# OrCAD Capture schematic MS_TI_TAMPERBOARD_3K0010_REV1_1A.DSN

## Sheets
1 Pg02: Tamper Test Board: size C; title: AM437x Tamper Test Board; rev: 1.1A; company: Texas Instruments; note: am437x_tamperboard_3k0010_rev1_1a.dsn; note: ARM MPU BU; note: Final
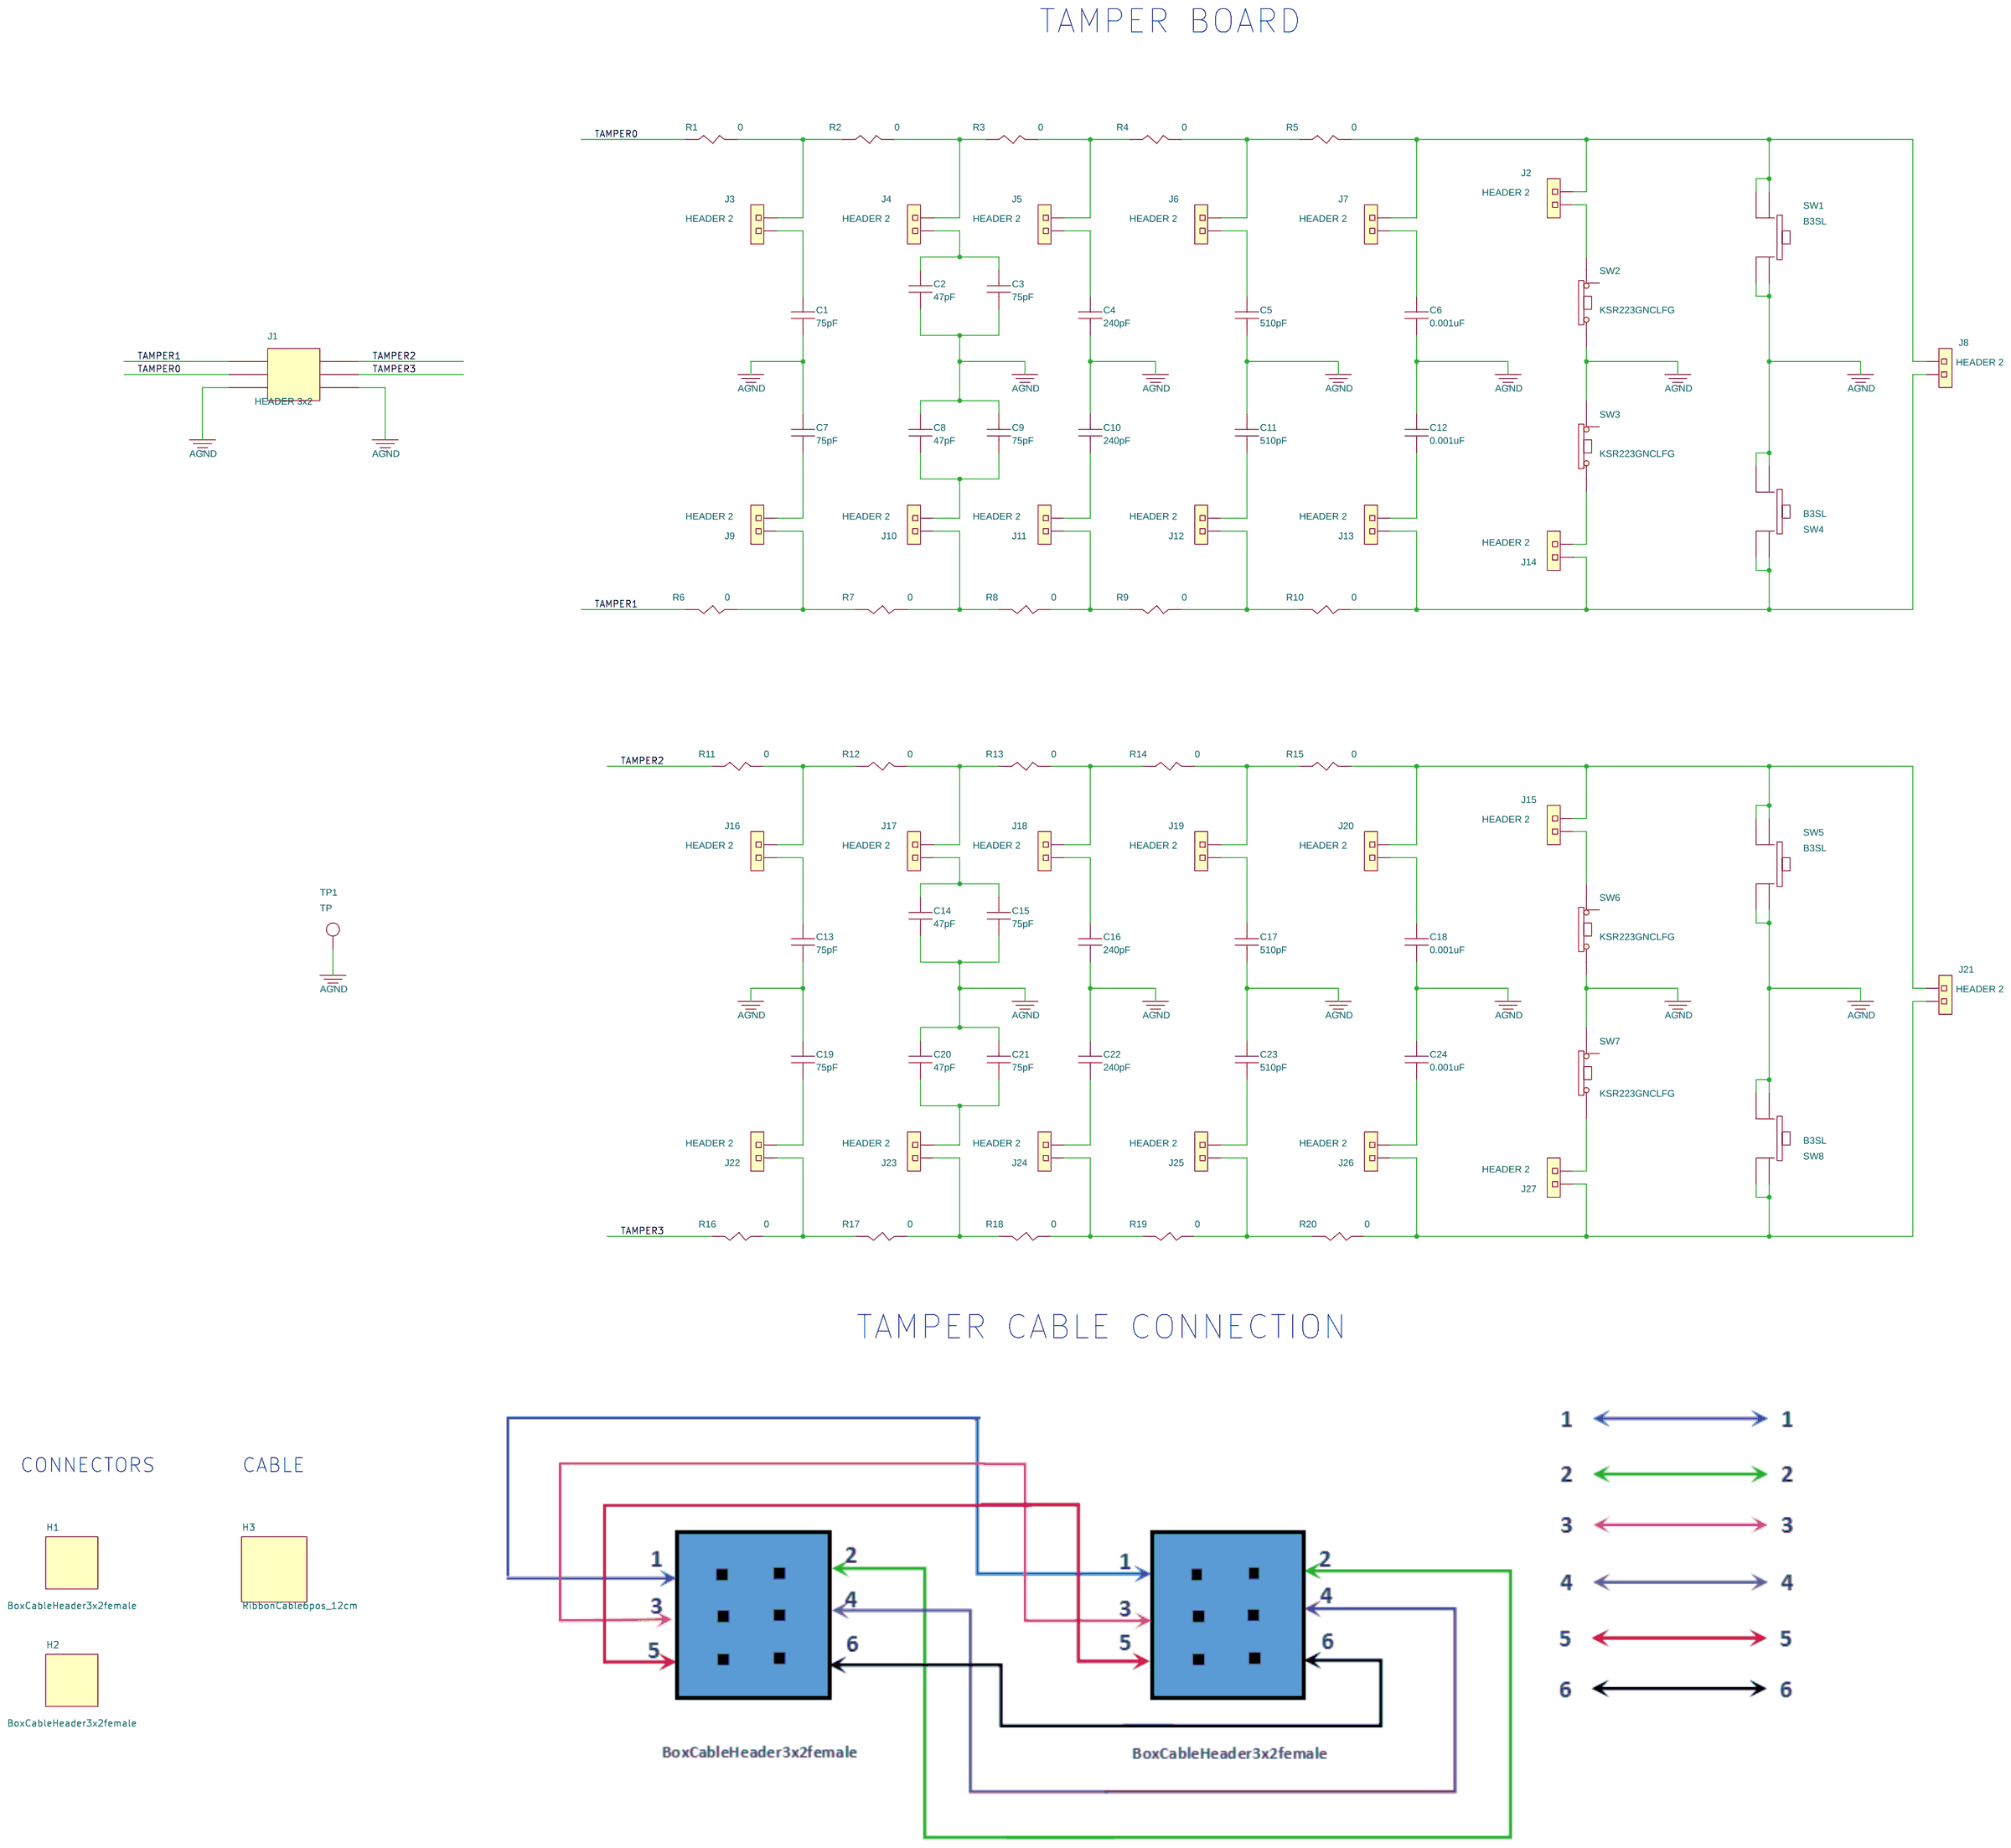
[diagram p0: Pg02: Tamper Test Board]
2 Pg01: Title
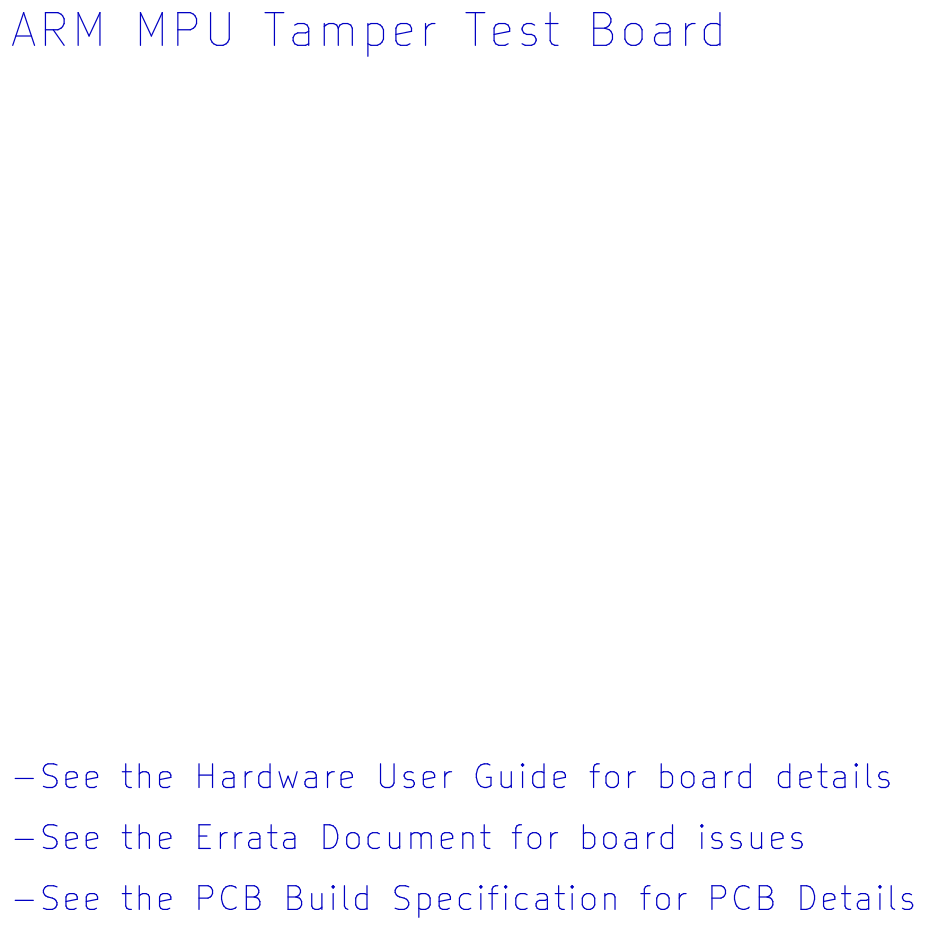
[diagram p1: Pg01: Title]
3 Pg03: Hardware Schematics
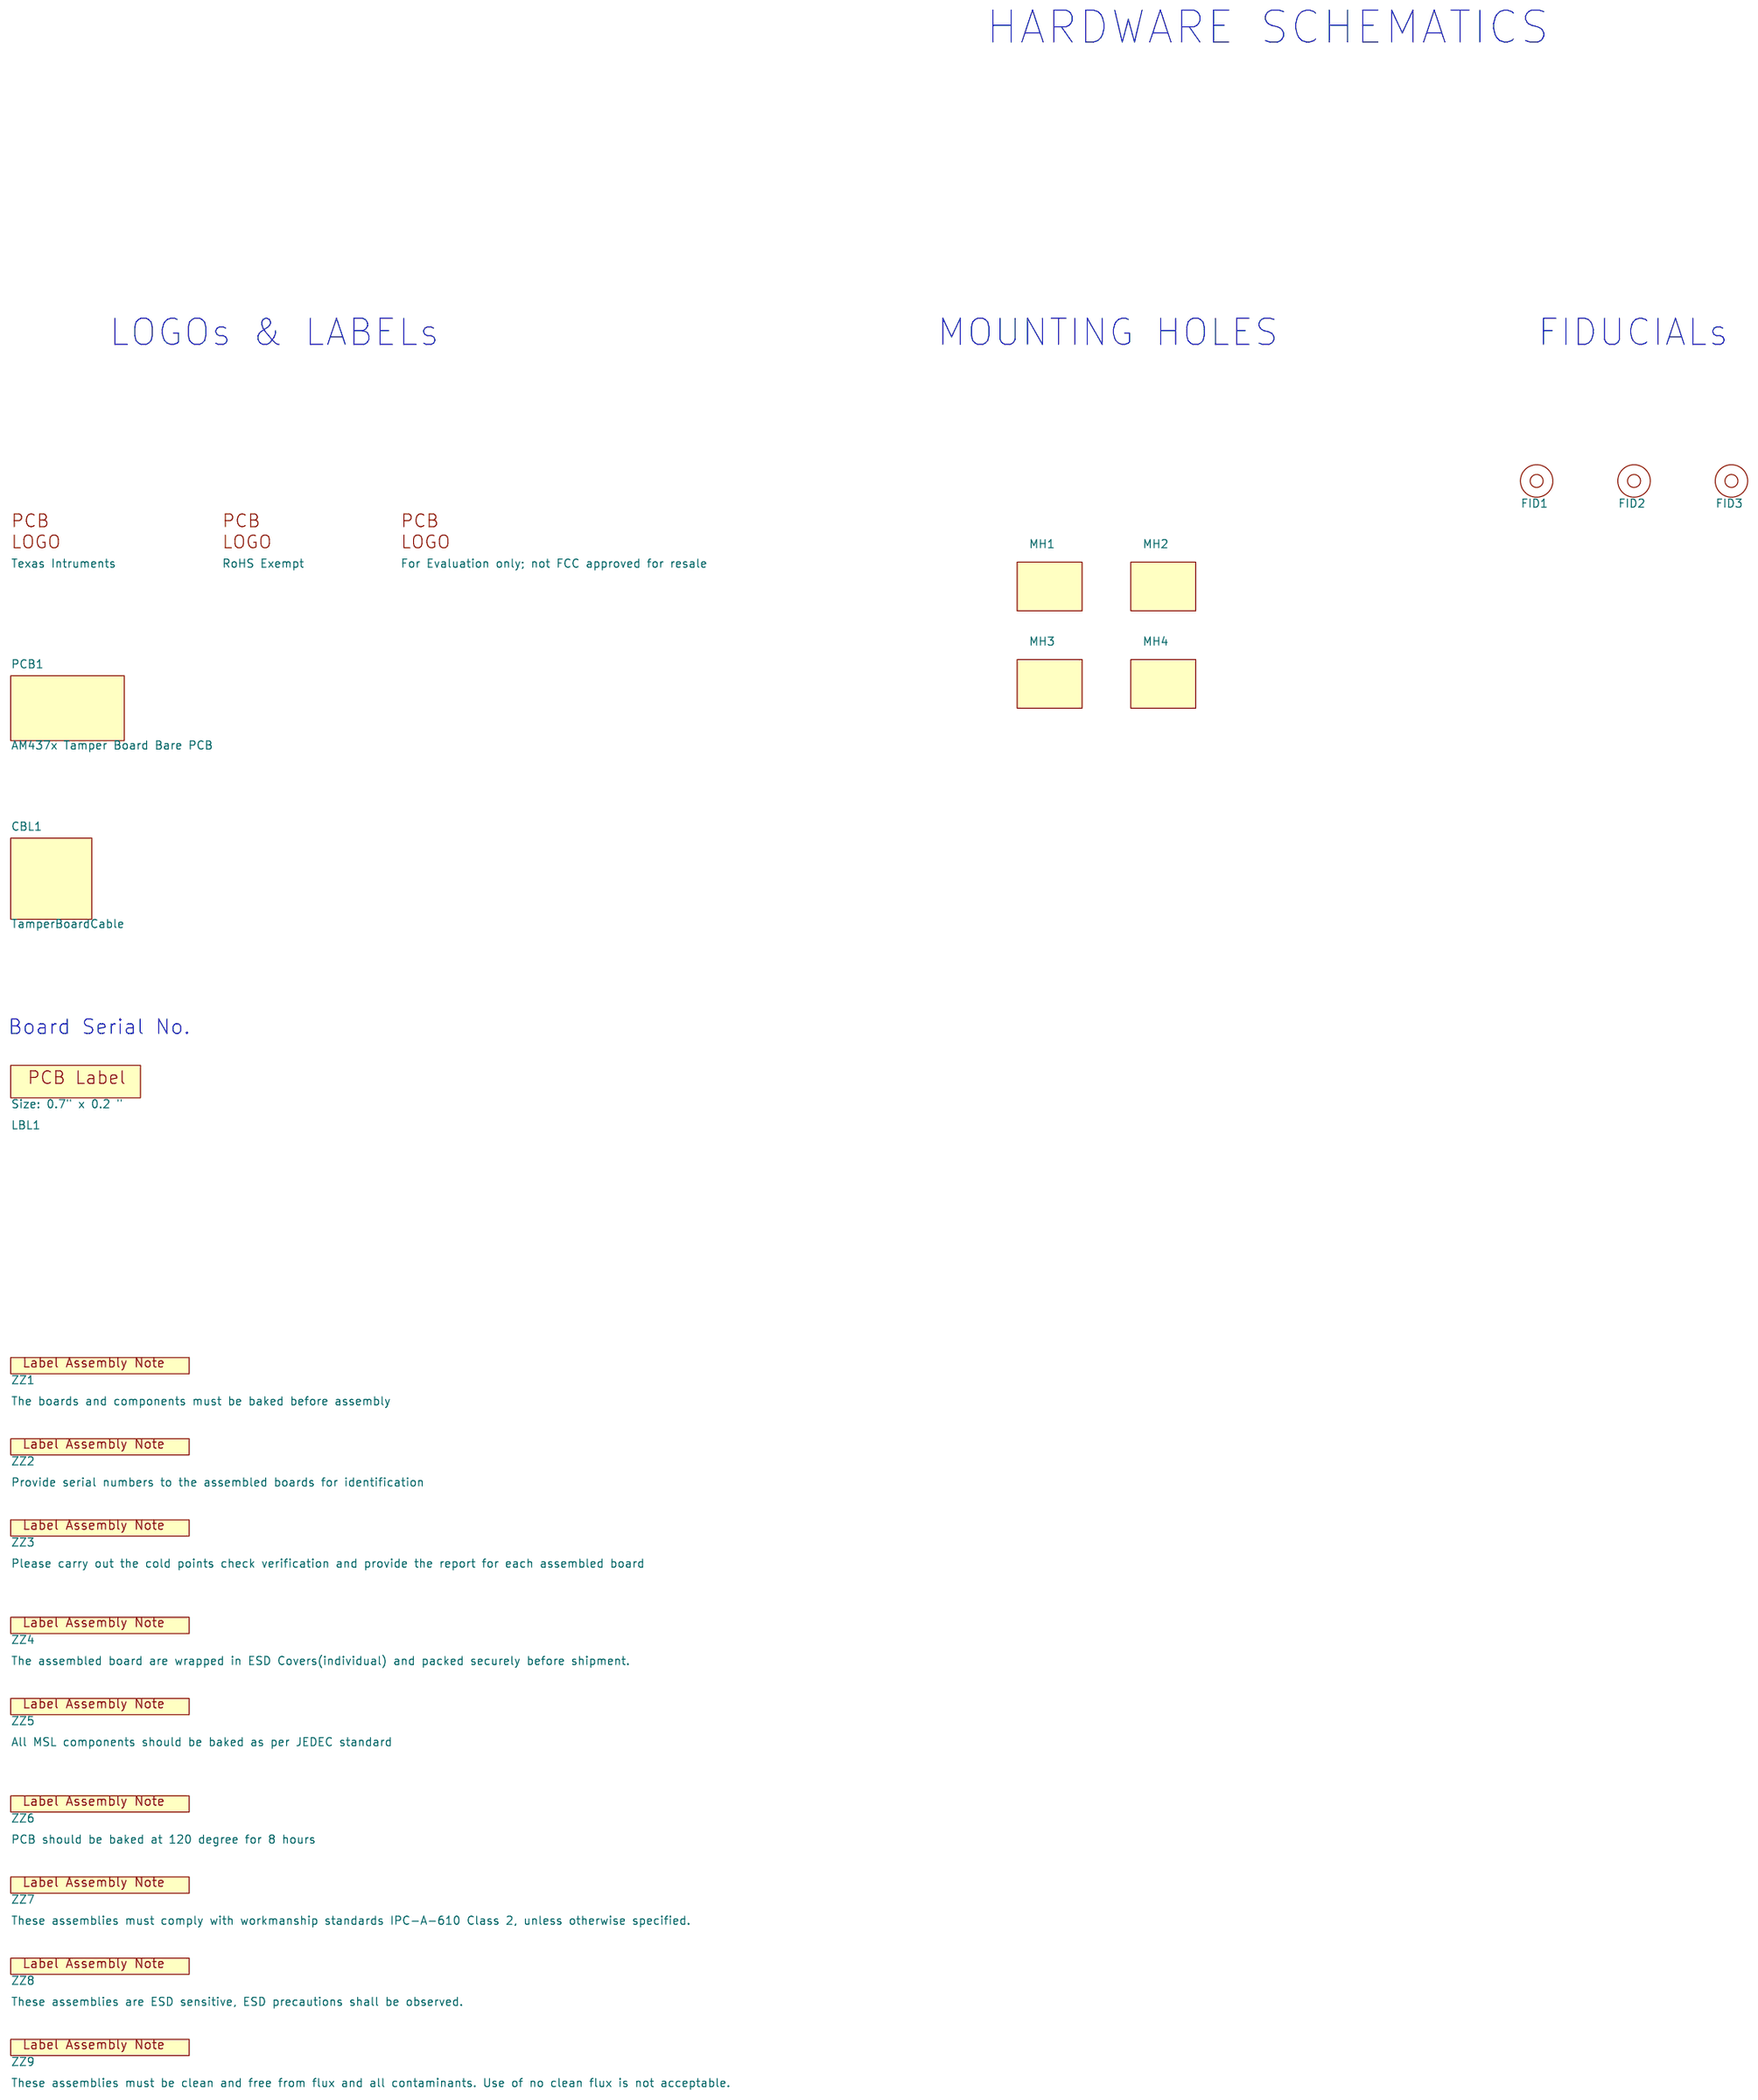
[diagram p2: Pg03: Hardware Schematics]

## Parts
sheet Pg02: Tamper Test Board
C1  75pF  [SM-7351-CAP-0402]
C2  47pF  [SM-7351-CAP-0402]
C3  75pF  [SM-7351-CAP-0402]
C4  240pF  [SM-7351-CAP-0402]
C5  510pF  [SM-7351-CAP-0603]
C6  0.001uF  [SM-7351-CAP-0402]
C7  75pF  [SM-7351-CAP-0402]
C8  47pF  [SM-7351-CAP-0402]
C9  75pF  [SM-7351-CAP-0402]
C10  240pF  [SM-7351-CAP-0402]
C11  510pF  [SM-7351-CAP-0603]
C12  0.001uF  [SM-7351-CAP-0402]
C13  75pF  [SM-7351-CAP-0402]
C14  47pF  [SM-7351-CAP-0402]
C15  75pF  [SM-7351-CAP-0402]
C16  240pF  [SM-7351-CAP-0402]
C17  510pF  [SM-7351-CAP-0603]
C18  0.001uF  [SM-7351-CAP-0402]
C19  75pF  [SM-7351-CAP-0402]
C20  47pF  [SM-7351-CAP-0402]
C21  75pF  [SM-7351-CAP-0402]
C22  240pF  [SM-7351-CAP-0402]
C23  510pF  [SM-7351-CAP-0603]
C24  0.001uF  [SM-7351-CAP-0402]
H1  BoxCableHeader3x2female  [DNP]
H2  BoxCableHeader3x2female  [DNP]
H3  RibbonCable6pos_12cm  [DNP]
J1  HEADER 3x2  [hdr2x3-330m]
J2  HEADER 2  [header_2x1]
J3  HEADER 2  [header_2x1]
J4  HEADER 2  [header_2x1]
J5  HEADER 2  [header_2x1]
J6  HEADER 2  [header_2x1]
J7  HEADER 2  [header_2x1]
J8  HEADER 2  [header_2x1]
J9  HEADER 2  [header_2x1]
J10  HEADER 2  [header_2x1]
J11  HEADER 2  [header_2x1]
J12  HEADER 2  [header_2x1]
J13  HEADER 2  [header_2x1]
J14  HEADER 2  [header_2x1]
J15  HEADER 2  [header_2x1]
J16  HEADER 2  [header_2x1]
J17  HEADER 2  [header_2x1]
J18  HEADER 2  [header_2x1]
J19  HEADER 2  [header_2x1]
J20  HEADER 2  [header_2x1]
J21  HEADER 2  [header_2x1]
J22  HEADER 2  [header_2x1]
J23  HEADER 2  [header_2x1]
J24  HEADER 2  [header_2x1]
J25  HEADER 2  [header_2x1]
J26  HEADER 2  [header_2x1]
J27  HEADER 2  [header_2x1]
R1  0  [SM-7351-RES-0402]
R2  0  [SM-7351-RES-0402]
R3  0  [SM-7351-RES-0402]
R4  0  [SM-7351-RES-0402]
R5  0  [SM-7351-RES-0402]
R6  0  [SM-7351-RES-0402]
R7  0  [SM-7351-RES-0402]
R8  0  [SM-7351-RES-0402]
R9  0  [SM-7351-RES-0402]
R10  0  [SM-7351-RES-0402]
R11  0  [SM-7351-RES-0402]
R12  0  [SM-7351-RES-0402]
R13  0  [SM-7351-RES-0402]
R14  0  [SM-7351-RES-0402]
R15  0  [SM-7351-RES-0402]
R16  0  [SM-7351-RES-0402]
R17  0  [SM-7351-RES-0402]
R18  0  [SM-7351-RES-0402]
R19  0  [SM-7351-RES-0402]
R20  0  [SM-7351-RES-0402]
SW1  B3SL  [SW_B3SL-1022P]
SW2  KSR223GNCLFG  [sw-tl3310]
SW3  KSR223GNCLFG  [sw-tl3310]
SW4  B3SL  [SW_B3SL-1022P]
SW5  B3SL  [SW_B3SL-1022P]
SW6  KSR223GNCLFG  [sw-tl3310]
SW7  KSR223GNCLFG  [sw-tl3310]
SW8  B3SL  [SW_B3SL-1022P]
TP1  TP  [TH_TP_5002]
sheet Pg03: Hardware Schematics
CBL1  TamperBoardCable  [DNP]
FID1  Fiducial  [Fiducial10-20]
FID2  Fiducial  [Fiducial10-20]
FID3  Fiducial  [Fiducial10-20]
LBL1  Size: 0.7" x 0.2 "  [Label_650x200]
LOGO1  Texas Intruments  [TI_Stacked_Overlay_Small]
LOGO3  RoHS Exempt  [TI_Stacked_Overlay_Small]
LOGO4  For Evaluation only; not FCC approved for resale  [FCC_disclaimer]
MH1  MH138NPL
MH2  MH138NPL
MH3  MH138NPL
MH4  MH138NPL
PCB1  AM437x Tamper Board Bare PCB  [DNP]
ZZ1  The boards and components must be baked before assembly  [AssemblyNoteLabel]
ZZ2  Provide serial numbers to the assembled boards for identification  [AssemblyNoteLabel]
ZZ3  Please carry out the cold points check verification and provide the report for each assembled board  [AssemblyNoteLabel]
ZZ4  The assembled board are wrapped in ESD Covers(individual) and packed securely before shipment.  [AssemblyNoteLabel]
ZZ5  All MSL components should be baked as per JEDEC standard  [AssemblyNoteLabel]
ZZ6  PCB should be baked at 120 degree for 8 hours  [AssemblyNoteLabel]
ZZ7  These assemblies must comply with workmanship standards IPC-A-610 Class 2, unless otherwise specified.  [AssemblyNoteLabel]
ZZ8  These assemblies are ESD sensitive, ESD precautions shall be observed.  [AssemblyNoteLabel]
ZZ9  These assemblies must be clean and free from flux and all contaminants. Use of no clean flux is not acceptable.  [AssemblyNoteLabel]

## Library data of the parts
C1 C3 C7 C9 C13 C15 C19 C21 = 1C_75pFCapacitor50V5%0402
C2 C8 C14 C20 = 1C_47pF50V5%SMD0402
C4 C10 C16 C22 = 1C_240pF25V5%SMD0402
C5 C11 C17 C23 = 1C_510pF50V5%SMD0603
C6 C12 C18 C24 = 1C_0.001uFCapacitor50V5%0402
H1 H2 = 2H_BoxConnector3x2female
H3 = 2T_RibbonCable6pos_12cm
J1 = 2H_Header3x2
J2-J27 = 2H_Header_2x1
R1-R20 = 1R_ZeroOhmResistor1_16W0402
SW1 SW4 SW5 SW8 = 2W_Switch_Pushbuttonsmd
SW2 SW3 SW6 SW7 = 2W_Switch_PushbuttonsmdNC: Mfr: C&K
TP1 = 2H_TestPointThroughHole
CBL1 = 4W_TamperBoard_Cable
FID1-FID3 = Fiducial
LBL1 = THT-14-423-10: Serail Number Label
LOGO1 LOGO3 = TI_Logo
LOGO4 = FCC_disclaimer
MH1-MH4 = MH
PCB1 = 3K_AM437xTamperBoard: Version: 1.0
ZZ1-ZZ9 = AssemblyNoteLabel_0

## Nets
AGND: C1.2 C2.2 C3.2 C4.2 C5.2 C6.2 C7.1 C8.1 C9.1 C10.1 C11.1 C12.1 C13.2 C14.2 C15.2 C16.2 C17.2 C18.2 C19.1 C20.1 C21.1 C22.1 C23.1 C24.1 J1.5 J1.6 SW1.3 SW1.4 SW2.2 SW3.1 SW4.3 SW4.4 SW5.3 SW5.4 SW6.2 SW7.1 SW8.3 SW8.4 TP1.1
TAMPER0: J1.3 R1.2(P2)
TAMPER1: J1.1 R6.2(P2)
TAMPER2: J1.2 R11.2(P2)
TAMPER3: J1.4 R16.2(P2)
N14106242: J2.1 J7.1 J8.1 R5.1(P1) SW1.1 SW1.2
N14106277: J8.2 J13.1 J14.1 R10.1(P1) SW4.1 SW4.2
N14106328: C1.1 J3.2
N14106335: J3.1 R1.1(P1) R2.2(P2)
N14106475: C2.1 C3.1 J4.2
N14106483: J4.1 R2.1(P1) R3.2(P2)
N14106696: C4.1 J5.2
N14106704: J5.1 R3.1(P1) R4.2(P2)
N14106768: C5.1 J6.2
N14106776: J6.1 R4.1(P1) R5.2(P2)
N14106938: C6.1 J7.2
N14107172: J2.2 SW2.1
N14109687: J9.1 R6.1(P1) R7.2(P2)
N14109707: C7.2 J9.2
N14109771: C8.2 C9.2 J10.2
N14109783: J10.1 R7.1(P1) R8.2(P2)
N14109827: C10.2 J11.2
N14109855: J11.1 R8.1(P1) R9.2(P2)
N14109919: J12.1 R9.1(P1) R10.2(P2)
N14109927: C11.2 J12.2
N14109975: C12.2 J13.2
N14110019: J14.2 SW3.2
N14115373: J21.2 J26.1 J27.1 R20.1(P1) SW8.1 SW8.2
N14115377: J22.1 R16.1(P1) R17.2(P2)
N14115401: C19.2 J22.2
N14115449: C20.2 C21.2 J23.2
N14115457: J23.1 R17.1(P1) R18.2(P2)
N14115489: C22.2 J24.2
N14115513: J24.1 R18.1(P1) R19.2(P2)
N14115561: J25.1 R19.1(P1) R20.2(P2)
N14115573: C23.2 J25.2
N14115605: C24.2 J26.2
N14115653: J27.2 SW7.2
N14115751: J15.1 J20.1 J21.1 R15.1(P1) SW5.1 SW5.2
N14115999: C14.1 C15.1 J17.2
N14116119: J16.1 R11.1(P1) R12.2(P2)
N14116123: C13.1 J16.2
N14116191: J17.1 R12.1(P1) R13.2(P2)
N14116235: C16.1 J18.2
N14116247: J18.1 R13.1(P1) R14.2(P2)
N14116295: J19.1 R14.1(P1) R15.2(P2)
N14116303: C17.1 J19.2
N14116359: C18.1 J20.2
N14116409: J15.2 SW6.1

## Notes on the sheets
sheet 1
- TAMPER BOARD
- TAMPER CABLE CONNECTION
- CONNECTORS
- CABLE
sheet 2
- ARM MPU Tamper Test Board
- -See the Hardware User Guide for board details
- -See the Errata Document for board issues
- -See the PCB Build Specification for PCB Details
sheet 3
- HARDWARE SCHEMATICS
- LOGOs & LABELs
- MOUNTING HOLES
- FIDUCIALs
- Board Serial No.
